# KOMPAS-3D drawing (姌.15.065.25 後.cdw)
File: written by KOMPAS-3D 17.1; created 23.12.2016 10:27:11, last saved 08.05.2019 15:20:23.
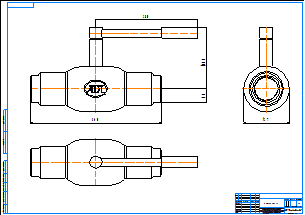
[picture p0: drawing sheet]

Sheet 1: A1, landscape

Title block, sheet 1: name: КШ.15.065.25 сс; material: Внимание! Данный продукт является объектом авторского права ООО «Торговый Дом АДЛ». / Запрещается изменение, копирование, распространение / (в том числе путем копирования на другие сайты и ресурсы в Интернете) / или любое иное использование информации и объектов без предварительного / согласия правообладателя (ООО «Торговый Дом АДЛ»).; sheets: 1; organisation: ООО "Торговый дом АДЛ"; sheet format: A1; stored path: C:\Users\tra\Desktop\2д чертежи\Шаровые краны БИВАЛ\КШ_Бивал_серия_14_15\KOMPAS_2D\КШ.15.065.25 сс.cdw

Views: Вид 1, Проекционный вид 2, Проекционный вид 3
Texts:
  Klimkovich
  ADL
Dimensions and other numbers on the sheet: 360; 280; 168,8; 38; 127; 1:1; 1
